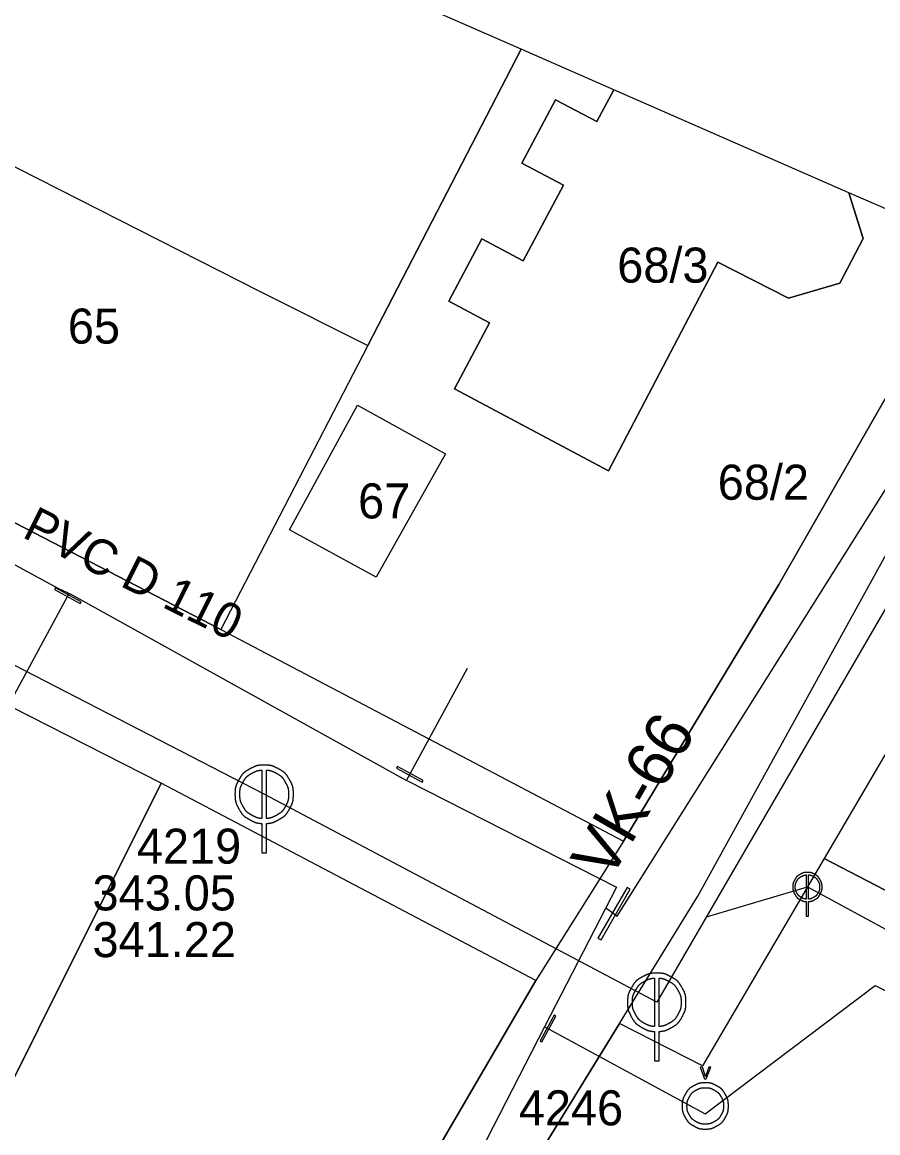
# Model space of a CAD drawing. Extents: x -559654 to -559448, y -1076607 to -1076478.
# Drawn here: x -559511.05 to -559474.44, y -1076580.66 to -1076533.13 of the extents above; entities that cross this region are included whole.
import ezdxf

# ---------------------------------------------------------------- set-up
doc = ezdxf.new("R2010")
doc.units = 0
for name, color, linetype in [('Armatura - popis', 7, 'Continuous'), ('Armatura vodovodní', 7, 'Continuous'), ('Default', 7, 'Continuous'), ('Kanalizační přípojka', 7, 'Continuous'), ('Kanalizační stoka', 7, 'Continuous'), ('Kanalizační šachta', 7, 'Continuous'), ('Parcela-polygon', 7, 'Continuous'), ('Parcela-text', 7, 'Continuous'), ('Popis šachty', 7, 'Continuous'), ('Vodovodní přípojka', 7, 'Continuous'), ('Vodovodní řad', 7, 'Continuous'), ('Vodovodní šachta', 7, 'Continuous'), ('Řad vodovodní popis', 7, 'Continuous')]:
    doc.layers.add(name, color=color, linetype=linetype)

msp = doc.modelspace()

# ---------------------------------------------------------------- linework, layer by layer
at = {"layer": 'Armatura vodovodní'}
for points in [[(-559508.573, -1076558.01), (-559508.536, -1076557.942), (-559509.635, -1076557.347), (-559509.673, -1076557.416)], [(-559493.934, -1076565.656), (-559493.896, -1076565.587), (-559494.996, -1076564.992), (-559495.033, -1076565.061)], [(-559486.285, -1076572.407), (-559485.033, -1076570.243), (-559485.168, -1076570.165), (-559486.42, -1076572.329)], [(-559488.818, -1076576.767), (-559488.222, -1076575.669), (-559488.291, -1076575.631), (-559488.887, -1076576.73)]]:
    msp.add_lwpolyline(points, close=True, dxfattribs=at)
at = {"layer": 'Default'}
for points in [[(-559500.698, -1076564.927), (-559500.91, -1076564.927), (-559501.115, -1076564.981), (-559501.313, -1076565.088)], [(-559500.084, -1076565.088), (-559500.283, -1076564.981), (-559500.488, -1076564.927), (-559500.698, -1076564.927)], [(-559501.78, -1076565.55), (-559501.892, -1076565.75), (-559501.948, -1076565.959), (-559501.948, -1076566.177)], [(-559501.313, -1076565.088), (-559501.512, -1076565.196), (-559501.667, -1076565.349), (-559501.78, -1076565.55)], [(-559501.601, -1076565.656), (-559501.509, -1076565.489), (-559501.379, -1076565.361), (-559501.213, -1076565.271)], [(-559501.213, -1076565.271), (-559501.07, -1076565.195), (-559500.932, -1076565.151), (-559500.801, -1076565.139)], [(-559500.595, -1076565.139), (-559500.464, -1076565.151), (-559500.327, -1076565.195), (-559500.185, -1076565.271)], [(-559500.185, -1076565.271), (-559500.019, -1076565.361), (-559499.889, -1076565.489), (-559499.796, -1076565.656)], [(-559499.616, -1076565.55), (-559499.729, -1076565.349), (-559499.885, -1076565.196), (-559500.084, -1076565.088)], [(-559499.448, -1076566.177), (-559499.448, -1076565.959), (-559499.504, -1076565.75), (-559499.616, -1076565.55)], [(-559501.74, -1076566.177), (-559501.74, -1076565.996), (-559501.694, -1076565.823), (-559501.601, -1076565.656)], [(-559499.796, -1076565.656), (-559499.702, -1076565.823), (-559499.656, -1076565.996), (-559499.656, -1076566.177)], [(-559501.948, -1076566.177), (-559501.948, -1076566.393), (-559501.893, -1076566.601), (-559501.783, -1076566.8)], [(-559501.604, -1076566.695), (-559501.695, -1076566.53), (-559501.74, -1076566.358), (-559501.74, -1076566.177)], [(-559499.656, -1076566.177), (-559499.656, -1076566.358), (-559499.701, -1076566.53), (-559499.792, -1076566.695)], [(-559499.613, -1076566.8), (-559499.503, -1076566.601), (-559499.448, -1076566.393), (-559499.448, -1076566.177)], [(-559501.783, -1076566.8), (-559501.673, -1076566.998), (-559501.519, -1076567.152), (-559501.321, -1076567.261)], [(-559501.218, -1076567.078), (-559501.384, -1076566.987), (-559501.513, -1076566.859), (-559501.604, -1076566.695)], [(-559499.792, -1076566.695), (-559499.883, -1076566.859), (-559500.011, -1076566.987), (-559500.176, -1076567.078)], [(-559500.075, -1076567.261), (-559499.877, -1076567.152), (-559499.723, -1076566.998), (-559499.613, -1076566.8)], [(-559501.321, -1076567.261), (-559501.146, -1076567.359), (-559500.973, -1076567.413), (-559500.801, -1076567.425)], [(-559500.801, -1076567.212), (-559500.937, -1076567.202), (-559501.076, -1076567.158), (-559501.218, -1076567.078)], [(-559500.176, -1076567.078), (-559500.319, -1076567.158), (-559500.459, -1076567.202), (-559500.595, -1076567.212)], [(-559500.595, -1076567.425), (-559500.423, -1076567.413), (-559500.25, -1076567.359), (-559500.075, -1076567.261)], [(-559477.993, -1076569.83), (-559478.049, -1076569.93), (-559478.077, -1076570.035), (-559478.077, -1076570.144)], [(-559477.759, -1076569.6), (-559477.859, -1076569.653), (-559477.936, -1076569.73), (-559477.993, -1076569.83)], [(-559477.902, -1076569.883), (-559477.856, -1076569.8), (-559477.791, -1076569.736), (-559477.708, -1076569.69)], [(-559477.452, -1076569.519), (-559477.558, -1076569.519), (-559477.66, -1076569.546), (-559477.759, -1076569.6)], [(-559477.708, -1076569.69), (-559477.636, -1076569.653), (-559477.568, -1076569.631), (-559477.503, -1076569.624)], [(-559477.144, -1076569.6), (-559477.243, -1076569.546), (-559477.346, -1076569.519), (-559477.452, -1076569.519)], [(-559477.4, -1076569.624), (-559477.334, -1076569.631), (-559477.265, -1076569.653), (-559477.195, -1076569.69)], [(-559477.195, -1076569.69), (-559477.112, -1076569.736), (-559477.047, -1076569.8), (-559477, -1076569.883)], [(-559476.911, -1076569.83), (-559476.967, -1076569.73), (-559477.045, -1076569.653), (-559477.144, -1076569.6)], [(-559476.827, -1076570.144), (-559476.827, -1076570.035), (-559476.855, -1076569.93), (-559476.911, -1076569.83)], [(-559478.077, -1076570.144), (-559478.077, -1076570.252), (-559478.049, -1076570.355), (-559477.994, -1076570.454)], [(-559477.972, -1076570.144), (-559477.972, -1076570.053), (-559477.949, -1076569.966), (-559477.902, -1076569.883)], [(-559477.903, -1076570.402), (-559477.949, -1076570.319), (-559477.972, -1076570.234), (-559477.972, -1076570.144)], [(-559477, -1076569.883), (-559476.953, -1076569.966), (-559476.929, -1076570.053), (-559476.929, -1076570.144)], [(-559476.929, -1076570.144), (-559476.929, -1076570.234), (-559476.952, -1076570.319), (-559476.998, -1076570.402)], [(-559476.909, -1076570.454), (-559476.854, -1076570.355), (-559476.827, -1076570.252), (-559476.827, -1076570.144)], [(-559477.994, -1076570.454), (-559477.938, -1076570.553), (-559477.861, -1076570.631), (-559477.762, -1076570.686)], [(-559477.711, -1076570.593), (-559477.794, -1076570.548), (-559477.858, -1076570.484), (-559477.903, -1076570.402)], [(-559477.762, -1076570.686), (-559477.676, -1076570.735), (-559477.589, -1076570.762), (-559477.503, -1076570.767)], [(-559477.503, -1076570.662), (-559477.571, -1076570.657), (-559477.641, -1076570.634), (-559477.711, -1076570.593)], [(-559477.191, -1076570.593), (-559477.262, -1076570.634), (-559477.332, -1076570.657), (-559477.4, -1076570.662)], [(-559477.4, -1076570.767), (-559477.314, -1076570.762), (-559477.227, -1076570.735), (-559477.139, -1076570.686)], [(-559476.998, -1076570.402), (-559477.043, -1076570.484), (-559477.108, -1076570.548), (-559477.191, -1076570.593)], [(-559477.139, -1076570.686), (-559477.04, -1076570.631), (-559476.963, -1076570.553), (-559476.909, -1076570.454)], [(-559484.515, -1076573.991), (-559484.714, -1076574.099), (-559484.869, -1076574.252), (-559484.982, -1076574.453)], [(-559483.9, -1076573.83), (-559484.112, -1076573.83), (-559484.317, -1076573.884), (-559484.515, -1076573.991)], [(-559484.415, -1076574.174), (-559484.272, -1076574.098), (-559484.134, -1076574.054), (-559484.003, -1076574.042)], [(-559483.286, -1076573.991), (-559483.485, -1076573.884), (-559483.69, -1076573.83), (-559483.9, -1076573.83)], [(-559483.797, -1076574.042), (-559483.666, -1076574.054), (-559483.529, -1076574.098), (-559483.387, -1076574.174)], [(-559482.818, -1076574.453), (-559482.931, -1076574.252), (-559483.087, -1076574.099), (-559483.286, -1076573.991)], [(-559484.982, -1076574.453), (-559485.094, -1076574.653), (-559485.15, -1076574.862), (-559485.15, -1076575.08)], [(-559484.942, -1076575.08), (-559484.942, -1076574.899), (-559484.896, -1076574.726), (-559484.803, -1076574.559)], [(-559484.803, -1076574.559), (-559484.711, -1076574.392), (-559484.581, -1076574.264), (-559484.415, -1076574.174)], [(-559483.387, -1076574.174), (-559483.221, -1076574.264), (-559483.091, -1076574.392), (-559482.998, -1076574.559)], [(-559482.998, -1076574.559), (-559482.904, -1076574.726), (-559482.858, -1076574.899), (-559482.858, -1076575.08)], [(-559482.65, -1076575.08), (-559482.65, -1076574.862), (-559482.706, -1076574.653), (-559482.818, -1076574.453)], [(-559485.15, -1076575.08), (-559485.15, -1076575.296), (-559485.095, -1076575.504), (-559484.985, -1076575.703)], [(-559484.806, -1076575.598), (-559484.897, -1076575.433), (-559484.942, -1076575.261), (-559484.942, -1076575.08)], [(-559482.858, -1076575.08), (-559482.858, -1076575.261), (-559482.903, -1076575.433), (-559482.994, -1076575.598)], [(-559482.815, -1076575.703), (-559482.705, -1076575.504), (-559482.65, -1076575.296), (-559482.65, -1076575.08)], [(-559484.985, -1076575.703), (-559484.875, -1076575.901), (-559484.721, -1076576.055), (-559484.523, -1076576.164)], [(-559484.42, -1076575.981), (-559484.586, -1076575.89), (-559484.715, -1076575.762), (-559484.806, -1076575.598)], [(-559484.003, -1076576.115), (-559484.139, -1076576.105), (-559484.278, -1076576.061), (-559484.42, -1076575.981)], [(-559483.378, -1076575.981), (-559483.521, -1076576.061), (-559483.661, -1076576.105), (-559483.797, -1076576.115)], [(-559482.994, -1076575.598), (-559483.085, -1076575.762), (-559483.213, -1076575.89), (-559483.378, -1076575.981)], [(-559483.277, -1076576.164), (-559483.079, -1076576.055), (-559482.925, -1076575.901), (-559482.815, -1076575.703)], [(-559484.523, -1076576.164), (-559484.348, -1076576.262), (-559484.175, -1076576.316), (-559484.003, -1076576.328)], [(-559483.797, -1076576.328), (-559483.625, -1076576.316), (-559483.452, -1076576.262), (-559483.277, -1076576.164)], [(-559481.816, -1076578.248), (-559481.818, -1076578.23), (-559481.822, -1076578.219), (-559481.826, -1076578.214)], [(-559481.802, -1076578.214), (-559481.807, -1076578.223), (-559481.811, -1076578.234), (-559481.816, -1076578.248)], [(-559482.312, -1076578.651), (-559482.469, -1076578.736), (-559482.592, -1076578.858), (-559482.681, -1076579.017)], [(-559482.5, -1076579.123), (-559482.429, -1076578.998), (-559482.332, -1076578.902), (-559482.207, -1076578.834)], [(-559481.826, -1076578.525), (-559481.993, -1076578.525), (-559482.154, -1076578.567), (-559482.312, -1076578.651)], [(-559482.207, -1076578.834), (-559482.083, -1076578.767), (-559481.956, -1076578.733), (-559481.826, -1076578.733)], [(-559481.339, -1076578.651), (-559481.498, -1076578.567), (-559481.66, -1076578.525), (-559481.826, -1076578.525)], [(-559481.826, -1076578.733), (-559481.694, -1076578.733), (-559481.566, -1076578.767), (-559481.442, -1076578.834)], [(-559481.442, -1076578.834), (-559481.318, -1076578.902), (-559481.22, -1076578.998), (-559481.15, -1076579.123)], [(-559480.968, -1076579.017), (-559481.057, -1076578.858), (-559481.181, -1076578.736), (-559481.339, -1076578.651)], [(-559482.681, -1076579.017), (-559482.77, -1076579.177), (-559482.814, -1076579.343), (-559482.814, -1076579.516)], [(-559482.606, -1076579.516), (-559482.606, -1076579.379), (-559482.57, -1076579.248), (-559482.5, -1076579.123)], [(-559481.15, -1076579.123), (-559481.079, -1076579.248), (-559481.044, -1076579.379), (-559481.044, -1076579.516)], [(-559480.835, -1076579.516), (-559480.835, -1076579.343), (-559480.88, -1076579.177), (-559480.968, -1076579.017)], [(-559482.814, -1076579.516), (-559482.814, -1076579.687), (-559482.77, -1076579.851), (-559482.682, -1076580.007)], [(-559482.501, -1076579.902), (-559482.571, -1076579.779), (-559482.606, -1076579.651), (-559482.606, -1076579.516)], [(-559481.044, -1076579.516), (-559481.044, -1076579.651), (-559481.078, -1076579.779), (-559481.148, -1076579.902)], [(-559480.965, -1076580.007), (-559480.878, -1076579.851), (-559480.835, -1076579.687), (-559480.835, -1076579.516)], [(-559482.682, -1076580.007), (-559482.595, -1076580.163), (-559482.472, -1076580.285), (-559482.315, -1076580.372)], [(-559482.213, -1076580.19), (-559482.336, -1076580.121), (-559482.432, -1076580.025), (-559482.501, -1076579.902)], [(-559481.826, -1076580.292), (-559481.961, -1076580.292), (-559482.089, -1076580.258), (-559482.213, -1076580.19)], [(-559481.437, -1076580.19), (-559481.56, -1076580.258), (-559481.69, -1076580.292), (-559481.826, -1076580.292)], [(-559481.148, -1076579.902), (-559481.217, -1076580.025), (-559481.314, -1076580.121), (-559481.437, -1076580.19)], [(-559481.331, -1076580.372), (-559481.173, -1076580.285), (-559481.052, -1076580.163), (-559480.965, -1076580.007)], [(-559482.315, -1076580.372), (-559482.158, -1076580.46), (-559481.995, -1076580.504), (-559481.826, -1076580.504)], [(-559481.826, -1076580.504), (-559481.653, -1076580.504), (-559481.488, -1076580.46), (-559481.331, -1076580.372)]]:
    msp.add_open_spline(points, degree=2, dxfattribs=at)
at = {"layer": 'Kanalizační přípojka'}
msp.add_lwpolyline([(-559481.775, -1076571.422), (-559477.452, -1076570.144), (-559468.198, -1076575.166)], dxfattribs=at)
at = {"layer": 'Kanalizační stoka'}
for points in [[(-559466.186, -1076544.589), (-559467.37, -1076546.62), (-559483.9, -1076575.08), (-559500.698, -1076566.177)], [(-559500.698, -1076566.177), (-559542.148, -1076544.787)]]:
    msp.add_lwpolyline(points, dxfattribs=at)
at = {"layer": 'Kanalizační šachta'}
for points in [[(-559500.801, -1076565.139), (-559500.801, -1076567.212)], [(-559500.595, -1076567.212), (-559500.595, -1076565.139)], [(-559500.801, -1076568.677), (-559500.595, -1076568.677), (-559500.595, -1076567.425)], [(-559500.801, -1076567.425), (-559500.801, -1076568.677)], [(-559477.503, -1076569.624), (-559477.503, -1076570.662)], [(-559477.4, -1076570.662), (-559477.4, -1076569.624)], [(-559477.503, -1076571.394), (-559477.4, -1076571.394), (-559477.4, -1076570.767)], [(-559477.503, -1076570.767), (-559477.503, -1076571.394)], [(-559484.003, -1076574.042), (-559484.003, -1076576.115)], [(-559483.797, -1076576.115), (-559483.797, -1076574.042)], [(-559484.003, -1076577.58), (-559483.797, -1076577.58), (-559483.797, -1076576.328)], [(-559484.003, -1076576.328), (-559484.003, -1076577.58)]]:
    msp.add_lwpolyline(points, dxfattribs=at)
at = {"layer": 'Parcela-polygon'}
for p, q in [((-559489.702, -1076534.288), (-559508.359, -1076526.116)), ((-559485.74, -1076536.024), (-559489.702, -1076534.288)), ((-559475.677, -1076540.432), (-559485.74, -1076536.024)), ((-559470.396, -1076542.745), (-559475.677, -1076540.432))]:
    msp.add_line(p, q, dxfattribs=at)
for points in [[(-559598.18, -1076518.16), (-559629.27, -1076502.23), (-559633.72, -1076500.39), (-559623.33, -1076497.36), (-559616.19, -1076501.28), (-559573.81, -1076522.62), (-559555.89, -1076531.62), (-559538.18, -1076540.8), (-559520.56, -1076549.81), (-559502.55, -1076559.13), (-559485.32, -1076568.19), (-559489.07, -1076574.14), (-559505.11, -1076565.7), (-559518.69, -1076558.79), (-559538.34, -1076548.73), (-559546.54, -1076544.48), (-559559.21, -1076537.91), (-559568.79, -1076532.99), (-559577, -1076528.76), (-559595.22, -1076519.64)], [(-559511.22, -1076539.4), (-559500.9, -1076544.64), (-559496.26, -1076546.97), (-559502.55, -1076559.13), (-559520.56, -1076549.81), (-559514.38, -1076537.81)], [(-559476.74, -1076568.93), (-559481.94, -1076577.8), (-559485.49, -1076575.98), (-559482.14, -1076570.54), (-559468.14, -1076545.12), (-559464.04, -1076547.27)], [(-559496.71, -1076549.53), (-559492.94, -1076551.61), (-559495.91, -1076556.88), (-559499.61, -1076554.86)]]:
    msp.add_lwpolyline(points, close=True, dxfattribs=at)
for points in [[(-559508.359, -1076526.116), (-559514.38, -1076537.81), (-559511.22, -1076539.4), (-559500.9, -1076544.64), (-559496.26, -1076546.97), (-559489.702, -1076534.288)], [(-559489.702, -1076534.288), (-559496.26, -1076546.97), (-559502.55, -1076559.13), (-559485.32, -1076568.19), (-559478.68, -1076557.2), (-559470.396, -1076542.745)], [(-559475.677, -1076540.432), (-559475.07, -1076542.39), (-559476.07, -1076544.3), (-559478.26, -1076544.94), (-559481.29, -1076543.41), (-559485.96, -1076552.34), (-559492.55, -1076548.83), (-559491.05, -1076546), (-559492.8, -1076545.07), (-559491.38, -1076542.4), (-559489.61, -1076543.34), (-559487.89, -1076540.11), (-559489.67, -1076539.17), (-559488.23, -1076536.45), (-559486.47, -1076537.39), (-559485.74, -1076536.024)], [(-559485.74, -1076536.024), (-559486.47, -1076537.39), (-559488.23, -1076536.45), (-559489.67, -1076539.17), (-559487.89, -1076540.11), (-559489.61, -1076543.34), (-559491.38, -1076542.4), (-559492.8, -1076545.07), (-559491.05, -1076546), (-559492.55, -1076548.83), (-559485.96, -1076552.34), (-559481.29, -1076543.41), (-559478.26, -1076544.94), (-559476.07, -1076544.3), (-559475.07, -1076542.39), (-559475.677, -1076540.432)], [(-559470.396, -1076542.745), (-559478.68, -1076557.2), (-559485.32, -1076568.19), (-559489.07, -1076574.14), (-559500.912, -1076594.458)], [(-559497.784, -1076596.071), (-559493.23, -1076588.57), (-559485.49, -1076575.98), (-559482.14, -1076570.54), (-559468.14, -1076545.12), (-559467.515, -1076544.007)], [(-559449.485, -1076554.911), (-559464.04, -1076547.27), (-559476.74, -1076568.93), (-559461.138, -1076577.031)], [(-559495.91, -1076556.88), (-559499.61, -1076554.86), (-559496.71, -1076549.53), (-559492.94, -1076551.61), (-559495.91, -1076556.88)], [(-559515.683, -1076586.846), (-559505.11, -1076565.7), (-559518.69, -1076558.79), (-559524.71, -1076570.87), (-559522.23, -1076572.11), (-559514.5, -1076576.01), (-559517.09, -1076580.05), (-559519.553, -1076584.851)], [(-559500.912, -1076594.458), (-559489.07, -1076574.14), (-559505.11, -1076565.7), (-559515.683, -1076586.846)], [(-559461.138, -1076577.031), (-559476.74, -1076568.93), (-559481.94, -1076577.8), (-559485.49, -1076575.98), (-559493.23, -1076588.57), (-559472.923, -1076599.402)]]:
    msp.add_lwpolyline(points, dxfattribs=at)
at = {"layer": 'Vodovodní přípojka'}
for points in [[(-559509.049, -1076557.576), (-559511.687, -1076562.451)], [(-559494.604, -1076565.581), (-559492.005, -1076560.778)], [(-559488.697, -1076576.122), (-559488.555, -1076576.199), (-559481.824, -1076579.848), (-559474.55, -1076574.36), (-559468.932, -1076577.152)]]:
    msp.add_lwpolyline(points, dxfattribs=at)
at = {"layer": 'Vodovodní řad'}
for points in [[(-559593.267, -1076491.395), (-559624.029, -1076495.839), (-559624.9, -1076495.951), (-559625.488, -1076496.027), (-559625.404, -1076497.654), (-559619.475, -1076500.701), (-559618.245, -1076501.333), (-559615.438, -1076502.776), (-559591.192, -1076515.237), (-559582.087, -1076519.916), (-559544.618, -1076539.173), (-559534.23, -1076544.512), (-559532.371, -1076545.439), (-559530.757, -1076546.244), (-559525.83, -1076548.702), (-559513.543, -1076555.186), (-559509.507, -1076557.365), (-559508.97, -1076557.619), (-559494.604, -1076565.581), (-559494.539, -1076565.616), (-559485.627, -1076570.145)], [(-559486.082, -1076571.032), (-559485.727, -1076571.286), (-559485.591, -1076571.397), (-559469.94, -1076546.51), (-559468.257, -1076543.682)], [(-559485.627, -1076570.145), (-559488.697, -1076576.122), (-559492.285, -1076583.109), (-559496.554, -1076590.087), (-559499.632, -1076595.118)]]:
    msp.add_lwpolyline(points, dxfattribs=at)
at = {"layer": 'Vodovodní šachta'}
for points in [[(-559481.826, -1076578.214), (-559481.949, -1076577.855), (-559482.045, -1076577.855), (-559481.85, -1076578.358)], [(-559481.85, -1076578.358), (-559481.782, -1076578.358), (-559481.584, -1076577.855), (-559481.672, -1076577.855), (-559481.802, -1076578.214)]]:
    msp.add_lwpolyline(points, dxfattribs=at)

# ---------------------------------------------------------------- texts
at = {"layer": 'Armatura - popis'}
msp.add_text('VK-66', height=2, rotation=59.9444, dxfattribs=at).set_placement((-559485.916, -1076569.931))
at = {"layer": 'Parcela-text'}
for s, p in [('68/3', (-559485.59, -1076544.28)), ('65', (-559509.1, -1076546.89)), ('68/2', (-559481.29, -1076553.57)), ('67', (-559496.68, -1076554.37))]:
    msp.add_text(s, height=1.5, dxfattribs=at).set_placement(p)
at = {"layer": 'Popis šachty'}
for s, p in [('4219', (-559506.146, -1076569.147)), ('343.05', (-559508.045, -1076571.147)), ('341.22', (-559508.045, -1076573.147)), ('4246', (-559489.801, -1076580.346))]:
    msp.add_text(s, height=1.5, dxfattribs=at).set_placement(p)
at = {"layer": 'Řad vodovodní popis'}
msp.add_text('PVC D 110', height=1.5, rotation=333.5006, dxfattribs=at).set_placement((-559511.104, -1076555.152))

doc.saveas('drawing.dxf')
